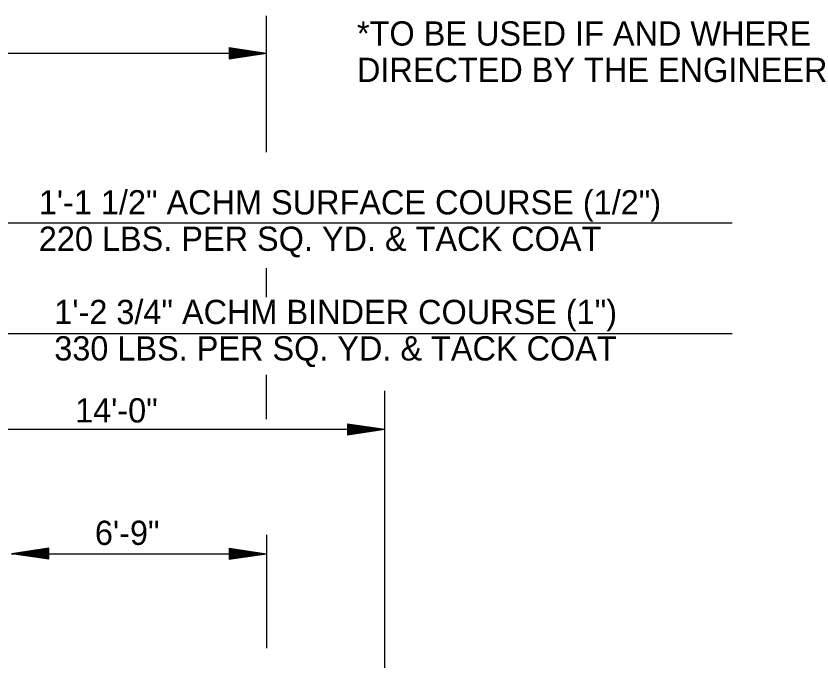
# Model space of a CAD drawing. Extents: x 6848689 to 6848907, y 1900908 to 1901005.
# Drawn here: x 6848761.22 to 6848782.55, y 1900929.37 to 1900946.63 of the extents above; entities that cross this region are included whole.
import ezdxf

# ---------------------------------------------------------------- set-up
doc = ezdxf.new("R2010")
doc.units = 0
doc.layers.add('R_Draft', color=7, linetype='Continuous')
doc.layers.add('R_No Plot', color=7, linetype='Continuous')

msp = doc.modelspace()

# ---------------------------------------------------------------- linework, layer by layer
at = {"layer": 'R_Draft'}
for p, q in [((6848766.936, 1900945.778), (6848767.936, 1900945.628)), ((6848766.936, 1900945.778), (6848766.936, 1900945.478)), ((6848766.936, 1900945.753), (6848767.769, 1900945.628)), ((6848766.936, 1900945.728), (6848767.597, 1900945.628)), ((6848766.936, 1900945.703), (6848767.43, 1900945.628)), ((6848766.936, 1900945.677), (6848767.261, 1900945.628)), ((6848766.936, 1900945.652), (6848767.094, 1900945.628)), ((6848766.936, 1900945.478), (6848767.936, 1900945.628)), ((6848766.936, 1900945.579), (6848767.261, 1900945.628)), ((6848766.936, 1900945.529), (6848767.597, 1900945.628)), ((6848766.936, 1900945.503), (6848767.769, 1900945.628)), ((6848766.936, 1900945.554), (6848767.43, 1900945.628)), ((6848766.936, 1900945.605), (6848767.094, 1900945.628)), ((6848770.103, 1900935.706), (6848771.103, 1900935.556)), ((6848770.103, 1900935.706), (6848770.103, 1900935.406)), ((6848770.103, 1900935.681), (6848770.936, 1900935.556)), ((6848770.103, 1900935.656), (6848770.764, 1900935.556)), ((6848770.103, 1900935.631), (6848770.598, 1900935.556)), ((6848770.103, 1900935.605), (6848770.428, 1900935.556)), ((6848770.103, 1900935.58), (6848770.261, 1900935.556)), ((6848770.103, 1900935.406), (6848771.103, 1900935.556)), ((6848770.103, 1900935.507), (6848770.428, 1900935.556)), ((6848770.103, 1900935.457), (6848770.764, 1900935.556)), ((6848770.103, 1900935.431), (6848770.936, 1900935.556)), ((6848770.103, 1900935.482), (6848770.598, 1900935.556)), ((6848770.103, 1900935.533), (6848770.261, 1900935.556)), ((6848762.1, 1900932.374), (6848761.1, 1900932.224)), ((6848762.1, 1900932.074), (6848761.1, 1900932.224)), ((6848762.1, 1900932.349), (6848761.267, 1900932.224)), ((6848762.1, 1900932.099), (6848761.267, 1900932.224)), ((6848762.1, 1900932.323), (6848761.439, 1900932.224)), ((6848762.1, 1900932.124), (6848761.439, 1900932.224)), ((6848762.1, 1900932.298), (6848761.605, 1900932.224)), ((6848762.1, 1900932.149), (6848761.605, 1900932.224)), ((6848762.1, 1900932.273), (6848761.775, 1900932.224)), ((6848762.1, 1900932.175), (6848761.775, 1900932.224)), ((6848762.1, 1900932.247), (6848761.942, 1900932.224)), ((6848762.1, 1900932.2), (6848761.942, 1900932.224)), ((6848762.1, 1900932.074), (6848762.1, 1900932.374)), ((6848766.936, 1900932.374), (6848767.936, 1900932.224)), ((6848766.936, 1900932.374), (6848766.936, 1900932.074)), ((6848766.936, 1900932.349), (6848767.769, 1900932.224)), ((6848766.936, 1900932.323), (6848767.597, 1900932.224)), ((6848766.936, 1900932.298), (6848767.43, 1900932.224)), ((6848766.936, 1900932.272), (6848767.261, 1900932.224)), ((6848766.936, 1900932.247), (6848767.094, 1900932.224)), ((6848766.936, 1900932.074), (6848767.936, 1900932.224)), ((6848766.936, 1900932.175), (6848767.261, 1900932.224)), ((6848766.936, 1900932.124), (6848767.597, 1900932.224)), ((6848766.936, 1900932.099), (6848767.769, 1900932.224)), ((6848766.936, 1900932.149), (6848767.43, 1900932.224)), ((6848766.936, 1900932.2), (6848767.094, 1900932.224))]:
    msp.add_line(p, q, dxfattribs=at)
at = {"layer": 'R_No Plot'}
for p, q in [((6848767.936, 1900942.982), (6848767.936, 1900946.627)), ((6848724.258, 1900945.628), (6848767.936, 1900945.628)), ((6848756.124, 1900941.082), (6848780.413, 1900941.082)), ((6848767.936, 1900939.096), (6848767.936, 1900939.871)), ((6848756.124, 1900938.117), (6848780.413, 1900938.117)), ((6848767.936, 1900935.826), (6848767.936, 1900937.016)), ((6848771.104, 1900928.081), (6848771.104, 1900936.583)), ((6848757.103, 1900935.556), (6848771.103, 1900935.556)), ((6848767.936, 1900932.728), (6848767.936, 1900929.696)), ((6848761.1, 1900932.224), (6848767.936, 1900932.224))]:
    msp.add_line(p, q, dxfattribs=at)

# ---------------------------------------------------------------- texts
at = {"layer": 'R_Draft'}
for s, p in [('*TO BE USED IF AND WHERE ', (6848770.36, 1900945.833)), ('DIRECTED BY THE ENGINEER', (6848770.36, 1900944.858)), ('1\'-1 1/2" ACHM SURFACE COURSE (1/2")', (6848761.835, 1900941.31)), ('220 LBS. PER SQ. YD. & TACK COAT', (6848761.835, 1900940.335)), ('1\'-2 3/4" ACHM BINDER COURSE (1")', (6848762.249, 1900938.373)), ('330 LBS. PER SQ. YD. & TACK COAT', (6848762.249, 1900937.398)), ('14\'-0"', (6848762.806, 1900935.738)), ('6\'-9"', (6848763.338, 1900932.458))]:
    msp.add_text(s, height=0.65, dxfattribs=at).set_placement(p)

doc.saveas('drawing.dxf')
